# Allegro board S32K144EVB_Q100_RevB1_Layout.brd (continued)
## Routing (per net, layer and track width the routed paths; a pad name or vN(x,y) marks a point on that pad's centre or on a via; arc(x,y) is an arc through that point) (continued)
P3V3: length 34.3
  TOP w0.381: U15.5 39.68,35.09 ; U15.5 39.68,34.14 ; U15.5 38.99,35.15 ; U15.5 38.99,34.08 ; U15.5 39.68,34.61 ; 42.67,31.97 TP13.1 ; TP13.1 42.56,32.44 ; TP13.1 43.6,32.91 ; TP13.1 43.13,31.87 ; TP13.1 42.67,32.91 ; TP13.1 43.6,31.97 ; TP13.1 43.13,33.01 ; TP13.1 43.71,32.44 ; J10.1 40.65,29.57 ; J10.1 39.57,30.65 ; J10.1 40.65,30.65 ; J10.1 40.65,28.49 ; J10.1 39.57,28.49 ; C24.1 44.04,30.33 ; C24.1 44.04,30.97 ; C24.1 42.51,30.33 ; C24.1 42.51,30.97 ; C24.1 43.27,30.97 ; R63.1 40.1,26.93 ; R63.1 39.46,27.69 ; R63.1 40.1,27.69
  L3_MIX w0.508: J3.7 36.54,5.12 ; J3.7 36.3,5.9 ; J3.7 34.51,5.12 ; J3.7 35.52,6.13 ; J3.7 34.74,5.9 ; J3.7 36.3,4.34 ; J3.7 34.74,4.34 ; 39.57,28.49 J10.1 ; J10.1 40.65,29.57 ; J10.1 40.39,28.74 ; J10.1 38.74,28.74 ; J10.1 40.39,30.39
P3V3_SDA: length 36
  TOP w0.178: U9.5 33.64,39.65 v1(33.64,39.64)
  TOP w0.254: R15.1 30.3,45.46 v1(30.04,45.2) ; 30.5,36.03 C19.1 31.01,35.52 ; U4.1 28.54,45.51 v1(28.2,45.85) 28.45,46.1 U2.7 ; C18.1 29.42,36.54 ; C18.1 29.93,36.03 ; C18.1 29.42,35.52 ; U8.1 v1(19.51,43.09) ; R1.2 v1(6.4,52.28) ; 9.19,50.89 R3.1 ; U7.1 28.13,41.66 27.86,41.93 v1(27.83,41.93) ; 15.64,40.52 16.01,40.88 16.58,40.88 16.94,40.52 ; J12.1 17.92,28.09 C26.1 ; 30.51,37.11 R52.1 ; U10.1 v1(27.41,38.62) ; v1(15.03,27.14) 14.52,27.14 14.44,27.06 R77.1 ; 9.19,49.94 C3.1 ; U1.1 9.07,51.26 ; U8.11 v1(16.65,37.9)
  TOP w0.508: J9.1 13.35,40.52 C12.1 15.64,40.52 ; R12.1 v1(25.56,46.72) ; R30.1 v1(30.99,42.98) ; v1(37.61,42.64) C10.1 37.61,41.46 R39.2 R42.1 ; R60.1 v1(11.75,37.33)
  TOP w0.635: C6.1 17.76,44.83 C7.1 18.65,43.95 v1(19.51,43.09)
  BOTTOM w0.254: 10.78,38.9 J9.1 ; J9.1 12.69,38.9 ; J9.1 11.73,37.94 ; 17.32,27.37 J12.1 18.65,28.09
  vias: v1(8.76,50.56) v1(29.29,36.97)
P5V0: length 35.8
  TOP w0.381: C21.1 31.6,32.09 ; C21.1 31.6,31.45 ; C21.1 30.84,31.45 ; TP14.1 31.72,29.54 ; TP14.1 30.78,29.54 ; TP14.1 31.82,29.07 ; TP14.1 30.78,28.6 ; TP14.1 30.68,29.07 ; TP14.1 31.72,28.6 ; TP14.1 31.25,28.5 ; TP14.1 31.25,29.64 ; 34.49,28.49 J10.3 ; J10.3 33.66,28.74 ; J10.3 33.66,30.39 ; J10.3 34.49,30.65 ; J10.3 33.41,29.57 ; 31.74,31.44 C22.1 ; C22.1 33.27,31.44 ; C22.1 32.5,31.44 ; C22.1 31.74,32.08 ; 33.9,26.93 R64.1 ; R64.1 33.9,27.69 ; R64.1 34.54,27.69
  TOP w0.635: R169.1 v3(34.1,34.61) ; U15.1 v3(35.25,34.61)
  L3_MIX w0.381: J3.9 38.84,5.9 ; J3.9 38.06,6.13 ; J3.9 37.28,5.9 ; J3.9 39.08,5.12 ; J3.9 37.28,4.34 ; J3.9 38.84,4.34
  BOTTOM w0.635: J10.3 35.57,29.57 ; J10.3 34.49,28.49 ; J10.3 33.41,29.57 ; J10.3 34.49,30.65 ; J107.2 25.24,30.65 ; J107.2 26.32,29.57 ; J107.2 24.16,29.57 ; J107.2 25.24,28.49
  vias: v1(41.68,26.63) v1(42,27.41) v1(42.39,26.64)
P5V0_SDA_USB_CONN_VBUS: length 5.6
  TOP w0.152: 7.34,41.44 7.34,41.45 D17.2 8.02,40.99
  TOP w0.356: 5.64,42.72 J7.1
  TOP w0.381: L1.1 8.02,40.99
  TOP w0.635: 5.64,42.72 6.92,41.44 7.34,41.44
P5V_SBC: length 59.2
  TOP w0.203: U28.1 44.26,24.42 43.79,23.95 43.79,23.39 v1(44.21,22.97) ; U26.1 36.78,24.42 ; U30.1 40.72,24.44 40.31,24.03 40.31,23.32 v1(40.65,22.97) ; 21.62,17.74 U19.5 ; U32.1 v1(43.74,19.05)
  TOP w0.254: U29.1 v1(48.98,24.65) 48.98,25.06 49.62,25.69 ; R560.2 41.24,22.9 ; R560.2 41.24,21.88 ; R560.2 v1(40.65,22.97) ; R560.2 40.73,22.39 ; R558.2 v1(44.21,22.97) ; R536.1 36.28,22.9 ; R536.1 34.76,22.9 ; R536.1 35.52,23.53 ; R562.2 v1(47.97,18.67) ; R556.2 37.68,22.9 ; R556.2 37.17,22.39 ; R556.2 v1(37.1,22.97) ; R556.2 37.68,21.88 ; 34.28,22.91 R538.1 33.65,23.67 ; 33.65,23.79 R530.1 33.65,25.32 ; 49.62,22.58 49.62,22.56 49.53,22.47 49.57,22.43 49.57,22.15 49.38,21.96 49.02,21.96 v1(48.94,21.88) 48.94,21.65 49.16,21.43 U31.1 ; R564.1 49.19,19.34 48.92,19.07 v1(48.92,18.77) 49.04,18.65 49.24,18.65 49.57,18.32 U33.1
  TOP w0.356: 21.62,17.74 21.82,17.74 22.5,17.05
  TOP w0.381: R530.1 v1(34.58,24.56)
  TOP w0.508: R538.1 v1(33.65,21.83)
  TOP w0.762: v2(24.02,14.14) TP15.1 24.03,15.62 R535.1 22.5,17.05
  TOP w0.889: J107.1 28.95,30.74 C27.1
  L3_MIX w1.27: J107.1 24.02,25.8 v2(24.02,14.14)
  BOTTOM w0.508: J107.1 28.86,30.65 ; J107.1 28.86,28.49 ; J107.1 27.78,30.65 ; J107.1 27.78,28.49 ; J107.1 28.86,29.57
P5V_SDA: length 24.5
  TOP w0.254: 22.16,45.36 R14.1 22.67,45.86 ; U8.6 16.74,41.43 v1(16.62,41.43)
  TOP w0.508: C25.1 v1(8.15,29.82) ; C15.1 7.5,37.47 7.18,37.79 v1(7.18,38.88) L1.2 ; U11.1 v1(8.08,31.93) ; R70.1 v1(8.14,31.06) ; R57.1 v1(26.57,37.38) ; C11.1 v1(9.35,38.48)
  L3_MIX w0.635: v1(16.62,41.43) v1(16.62,45.82)
  BOTTOM w0.254: v1(26.57,37.38) 25.9,38.05 25.9,38.08 25.53,38.45 25.5,38.45 24.74,39.21 23.1,39.21 22.47,39.84 22.47,45.44 v1(22.02,45.89)
  vias: v1(7.36,46.09) v1(8.23,46.11) v1(9.16,46.11)
P5V_SDA_PSW: length 26.2
  TOP w0.508: v1(7.96,27.05) 7.26,27.75 7.26,34.41 8.08,35.23 U11.6
  BOTTOM w0.508: v1(7.96,27.05) 9.59,27.05 11.2,25.44 18.58,25.44 J107.3
VBATT: length 68.8
  TOP w0.381: D9.A 26.48,12.42 ; D9.A 24.88,12.42 ; D9.A 25.68,12.42 ; D9.A 24.88,11.62 ; D9.A 26.48,10.82 ; D9.A 26.48,11.62 ; D9.A 24.88,10.82 ; D9.A 25.68,10.82 ; TP38.1 26.15,8.58 ; TP38.1 26.26,9.05 ; TP38.1 26.15,9.52 ; TP38.1 25.69,9.62 ; TP38.1 25.69,8.48 ; TP38.1 25.22,9.52 ; TP38.1 25.22,8.58 ; TP38.1 25.12,9.05 ; J16.1 23.2,7.96 ; J16.1 23.2,9.88 ; J16.1 21.83,7.96 ; J16.1 22.29,11.8 ; J16.1 22.75,11.8 ; J16.1 22.29,7.96 ; J16.1 23.2,10.84 ; J16.1 23.2,11.8
  BOTTOM w1.016: v2(23.93,7.2) 12.91,7.2 11.23,8.89 10.21,8.89 4.8,14.29 4.8,31.29 J11.2
VDD: length 128.2
  TOP w0.203: U30.8 41.36,25.28 40.91,25.73 v1(40.91,25.71) ; v1(44.44,20.36) 44.53,20.26 44.66,20.26 44.91,20.01 U32.8 ; U26.8 37.38,25.07 v1(37.12,25.33) ; U28.8 44.9,25.42 v1(44.51,25.81)
  TOP w0.254: R63.2 37.94,27.69 ; R63.2 37.3,26.93 ; R63.2 37.3,27.69 ; J10.2 37.85,28.74 ; J10.2 37.03,28.49 ; J10.2 35.95,29.57 ; J10.2 37.85,30.39 ; J10.2 36.2,30.39 ; J10.2 37.03,30.65 ; J10.2 38.11,29.57 ; J10.2 36.2,28.74 ; R64.2 36.06,27.69 ; R64.2 36.7,26.93 ; R64.2 36.7,27.69 ; U29.6 v1(51.19,24.65) ; U33.6 v1(51.27,18.32) ; v1(52.71,21.44) C537.1 51.39,21.44 51.38,21.43 U31.6
  TOP w0.508: J15.1 47.34,30.64 ; J15.1 47.34,28.51 ; J15.1 46.27,30.64 ; J15.1 48.4,28.51 ; J15.1 48.4,29.58 ; J15.1 46.27,29.58 ; J15.1 46.27,28.51 ; J15.1 48.4,30.64 ; 47.72,32.58 R117.1 ; R117.1 48.35,31.82 ; R117.1 48.35,33.34 ; 47.4,37.77 R121.1 ; R121.1 48.17,37.13 ; R121.1 48.93,37.77 ; 42.4,36.09 TP9.1 ; TP9.1 43.87,37.57 ; TP9.1 43.13,37.78 ; TP9.1 44.09,36.83 ; TP9.1 43.87,36.09 ; TP9.1 42.4,37.57 ; TP9.1 42.18,36.83 ; SW3.4 v1(124.13,19.63) ; SW2.4 v1(124.13,30.97) ; SW2.2 v1(124.13,38.79) ; 46.47,26.94 R56.2 ; R56.2 47.1,26.18 ; R56.2 47.1,27.7 ; SW3.2 v1(124.13,27.21) ; J14.1 54.49,38.57 ; J14.1 54.49,39.29 ; J14.1 53.16,38.57 ; SH1.2 40.46,38.74 ; SH1.2 40.46,37.55 ; SH1.2 41.15,38.15
  TOP w0.635: J3.3 C49.1 ; D11.A3 v3(119.42,15.91) ; D11.A2 v3(121.52,15.9) ; D11.A1 v3(123.62,16.02)
  L3_MIX w0.508: 42.18,36.83 TP9.1 ; TP9.1 43.87,37.57 ; TP9.1 42.4,36.09 ; TP9.1 43.13,37.78 ; TP9.1 44.09,36.83 ; TP9.1 42.4,37.57 ; TP9.1 43.13,35.88 ; TP9.1 43.87,36.09 ; J10.2 37.85,30.39 ; J10.2 36.2,28.74 ; J10.2 36.2,30.39 ; J10.2 37.03,30.65 ; J10.2 35.95,29.57 ; 29.66,5.9 J3.3 ; J3.3 29.43,5.12 ; J3.3 29.66,4.34 ; J3.3 30.44,6.13 ; J3.3 30.44,4.1
  BOTTOM w0.381: 83,1.8 J5.10 ; J5.10 84.56,3.36 ; J5.10 83.78,1.56 ; J5.10 84.8,2.58 ; J5.10 84.56,1.8 ; J5.10 83,3.36 ; J5.10 82.77,2.58 ; J5.10 83.78,3.59 ; 122.78,28.47 TP16.1 ; TP16.1 123.52,28.25 ; TP16.1 122.78,29.94 ; TP16.1 124.47,29.2 ; TP16.1 124.25,28.47 ; TP16.1 123.52,30.16 ; TP16.1 122.56,29.2 ; TP16.1 124.25,29.94 ; 80.46,55.14 J6.10 ; J6.10 81.24,54.9 ; J6.10 82.26,55.92 ; J6.10 80.23,55.92 ; J6.10 82.02,55.14 ; J6.10 80.46,56.7 ; J6.10 82.02,56.7 ; J6.10 81.24,56.93 ; TP4.1 114.91,55.87 ; TP4.1 113,55.87 ; TP4.1 113.96,56.82 ; TP4.1 113.22,56.6 ; TP4.1 113.96,54.91 ; TP4.1 114.69,55.13 ; TP4.1 114.69,56.6 ; TP4.1 113.22,55.13 ; R13.1 121.85,47.77 ; R13.1 120.84,49.8 ; R13.1 120.84,47.77 ; R13.1 119.82,49.8 ; R13.1 119.82,47.77 ; R13.1 119.82,48.78 ; R13.1 121.85,49.8 ; R13.1 121.85,48.78
  BOTTOM w0.635: J15.1 48.4,29.58 ; J15.1 46.27,29.58 ; J15.1 47.34,28.51
  vias: v1(70.2,1.09) v1(70.21,3.11) v1(70.23,2.07) v1(71.4,1.12) v1(71.43,3.09) v1(71.42,2.06)
VDD_MCU: length 75.7
  TOP w0.254: R103.1 58.95,32.98 ; R103.1 58.18,33.62 ; R103.1 57.42,33.62 ; R103.1 58.95,33.62 ; R103.1 57.42,32.98 ; C131.1 58.87,37.66 ; C131.1 59.51,36.89 ; C131.1 59.51,36.13 ; C131.1 58.87,36.13 ; C131.1 59.51,37.66 ; 59.04,33.63 R99.1 ; R99.1 60.56,32.99 ; R99.1 60.56,33.63 ; R99.1 59.8,33.63 ; R99.1 59.04,32.99 ; 62.15,32.78 C140.1 ; C140.1 62.58,32.69 ; C140.1 63,32.78 ; C140.1 63.08,33.2 ; C140.1 62.07,33.2 ; C147.1 59.51,41.83 ; C147.1 58.23,40.3 ; C147.1 58.23,41.06 ; C147.1 58.87,40.3 ; C147.1 59.51,40.3 ; C147.1 59.51,41.06 ; C147.1 58.23,41.83 ; C147.1 58.87,41.83 ; C43.1 59.51,38.57 ; C43.1 59.51,39.33 ; C43.1 58.87,39.33 ; C43.1 58.87,37.81 ; C43.1 59.51,37.81 ; 75.37,19.77 U17.38 ; 84.68,28.16 U17.61 81.54,28.16 ; 63.16,33.2 C145.1 ; C145.1 64.09,32.78 ; C145.1 63.24,32.78 ; C145.1 63.67,32.69 ; C145.1 64.18,33.2 ; C129.1 59.51,35.98 ; C129.1 58.87,34.46 ; C129.1 58.87,35.98 ; C129.1 59.51,35.22 ; C129.1 59.51,34.46 ; 60.97,33.2 C144.1 ; C144.1 61.06,33.63 ; C144.1 61.06,32.78 ; C144.1 61.48,32.69 ; C144.1 61.91,32.78 ; C144.1 61.99,33.2 ; 75.87,38.75 U17.87
  TOP w0.381: C142.1 75.62,39 75.87,38.75 ; 75.37,19.77 75.62,19.51 C141.1 ; 84.68,28.16 84.91,28.39 C143.1
  TOP w0.508: C146.1 86.48,28.55 86.31,28.39 C143.1
  TOP w0.635: C141.1 75.62,18.53 v3(75.2,18.11) 75.24,18.07 C137.1 ; v3(75.12,28.16) 81.54,28.16 ; C133.1 77.02,41.8 v3(75.62,40.4) C142.1
  TOP w0.762: R117.2 J15.2
  BOTTOM w0.508: v1(68.89,30.41) v3(65.79,30.41)
  BOTTOM w1.016: J15.2 49.88,31.27 51.29,32.68 51.44,32.68 52,33.25 55.53,33.25 55.98,33.69 56.24,33.95 v2(57.38,33.95)
  vias: v3(75.12,30.66)
VIN: length 28.4
  TOP w0.762: J3.1 27.9,7.51 29.8,9.41 34.04,9.41 35.78,7.67 43.13,7.67 J3.15
  TOP w0.889: J3.15 D13.A
ADC0_SE12: length 72.4
  TOP w0.16: R13.2 C5.1 116.26,44.77 116.26,44.76 TP5.1 116.26,30.84 114.98,29.56 100.58,29.56 97.86,26.84 v1(94.68,26.84) ; R164.2 v1(80.45,13.79)
  L3_MIX w0.16: v1(94.68,26.84) 94.68,25.27 94.03,24.62 v1(94.03,13.65)
  BOTTOM w0.16: v1(94.03,13.65) 93.03,13.65 92.92,13.75 89.82,13.75 89.02,14.55 85.91,14.55 84.85,13.49 82.47,13.49 82.45,13.47 80.78,13.47 v1(80.45,13.79)
AREF: length 43.9
  TOP w0.508: R109.2 55.67,44.7 53.43,46.94 40.09,46.94 39.62,46.47 35.48,46.47 32.64,49.31 27.9,49.31 J2.15
BTN0: length 58.6
  TOP w0.16: R152.2 v1(84.64,14.09) ; SW2.1 SW2.3 R44.1 119.9,31.82 119.89,31.82 C16.1 118.39,31.29 115.42,28.32 100.37,28.32 97.97,25.92 v1(93.98,25.92)
  L3_MIX w0.16: v1(93.98,25.92) 93.41,25.35 v1(93.41,14.62)
  BOTTOM w0.16: v1(93.41,14.62) 89.55,14.62 89.27,14.9 85.45,14.9 v1(84.64,14.09)
BTN1: length 61.2
  TOP w0.16: R153.2 v1(82.96,12.3) ; SW3.3 SW3.1 R74.1 C28.1 100.15,27.15 98.06,25.06 v1(95.43,25.06)
  L3_MIX w0.16: v1(94.57,12.95) 94.57,24.21 v1(95.43,25.06)
  BOTTOM w0.16: v1(82.96,12.3) 85.12,12.3 85.6,12.79 86.92,12.79 86.95,12.76 87.37,12.76 87.45,12.84 92.53,12.84 92.54,12.83 92.92,12.83 93.04,12.95 v1(94.57,12.95)
CAN_HI: length 21.5
  TOP w0.305: J13.1 1.5,21.91 1.5,20.02 2.14,19.37 3.9,19.37 4.22,19.04 TP19.1 6.75,19.04 6.87,19.16 7.95,19.16 10.37,16.74 12.09,16.74 J109.1 15.01,16.74 U19.18
CAN_LO: length 16.2
  TOP w0.305: J13.2 TP22.1 6.85,19.92 7.87,19.92 10.35,17.44 12.28,17.44 J108.1 15.02,17.24 U19.17
JTAG_TCLK/SWD_CLK: length 37
  TOP w0.16: J14.4 47.49,40.56 TP31.1 43.87,44.19 J8.2 ; R127.2 v1(69.45,44.33)
  BOTTOM w0.16: J14.4 50.52,40.56 50.49,40.53 50.49,38.55 51.28,37.75 53.36,37.75 53.68,38.07 54.51,38.09 54.52,38.09 59.28,42.85 67.96,42.85 v1(69.45,44.33)
JTAG_TDI: length 24.3
  TOP w0.16: v1(71.12,44.36) R128.2 ; R120.2 v1(49.41,45.66)
  BOTTOM w0.16: v1(71.12,44.36) 70.31,45.17 56.88,45.17 56.39,45.66 v1(49.41,45.66)
JTAG_TDO: length 29.8
  TOP w0.16: v1(73.37,45.16) 73.37,43.98 73.37,43.98 R123.2 ; R119.2 v1(47.85,46.31)
  BOTTOM w0.16: v1(47.85,46.31) 48.22,46.67 57.01,46.67 57.35,46.33 71.58,46.33 72.75,45.16 v1(73.37,45.16)
JTAG_TMS/SWD_DIO_PTA4: length 27.3
  TOP w0.16: v1(66.34,43.33) R122.2 ; J14.2 R121.2 TP34.1 46.34,39.29 J106.2
  BOTTOM w0.16: J14.2 52.79,38.39 53.52,38.39 53.54,38.41 54.01,38.42 58.92,43.33 v1(66.34,43.33)
LEDRGB_BLUE: length 4.9
  TOP w0.16: D11.C3 TP28.1 v1(117.69,7.48) R95.1
LEDRGB_GREEN: length 7.7
  TOP w0.16: R96.1 v1(117.67,5.7) 119.74,5.7 TP29.1 D11.C2
LEDRGB_RED: length 10.5
  TOP w0.16: D11.C1 TP30.1 v1(122.71,6.58) 120.06,3.93 R97.1
LIN: length 29.8
  TOP w0.406: U21.6 R171.1 R80.1 TP18.1 5.51,26.03 C17.1 J11.1
LIN_RX: length 43.3
  TOP w0.16: R130.1 69.87,14.15 68.15,12.43 51.99,12.43 51.65,12.09 46.93,12.09 45.95,13.07 45.95,15.23 47.99,17.27 v1(48.5,17.27) ; v1(48.5,22.75) 48.12,23.13 48.12,24.05 46.84,25.33 46.28,25.33 45.98,25.63 45.48,25.63 45.3,25.46 U28.7
  L3_MIX w0.16: v1(48.5,17.27) 48.86,17.63 49.03,17.63 49.38,17.98 49.38,19.43 48.48,20.32 48.48,22.07 48.5,22.09 v1(48.5,22.75)
LIN_RX_LS: length 35.7
  TOP w0.16: v1(32.12,21.85) R538.2 TP35.1 29.78,22.91 29.76,22.89 U21.1 ; U28.2 v1(44.37,23.77)
  L3_MIX w0.16: v1(43.88,14.35) 43.88,16.46 44.9,17.48 44.9,22.74 44.82,22.81 44.82,23.32 v1(44.37,23.77) ; v1(32.12,21.85) 32.6,21.37 32.6,19.72 32.43,19.56 v1(32.43,13.88)
  BOTTOM w0.16: v1(32.43,13.88) 43.41,13.88 v1(43.88,14.35)
LIN_SLP: length 43.5
  TOP w0.16: v1(48.02,24.81) 47.17,25.66 47.04,25.66 47.04,25.67 46.42,25.67 46.05,26.04 45.17,26.04 44.89,26.32 42.72,26.32 42.57,26.17 39.75,26.17 39.73,26.15 32.85,26.15 32.12,25.43 R530.2 29.98,24.56 29.59,24.16 U21.2 ; R529.1 61.4,18.66 59.99,17.26 55.17,17.26 54.13,18.3 v1(52.36,18.3)
  L3_MIX w0.16: v1(52.36,18.3) 51.57,19.09 51.57,22.12 52.2,22.74 52.2,24.29 51.35,25.14 48.35,25.14 v1(48.02,24.81)
LIN_TX: length 31.2
  TOP w0.16: v1(51.74,16.58) 52.07,16.25 52.07,16.05 55.35,12.76 64.75,12.76 65.32,13.33 67.34,13.33 68.2,14.18 R131.1 ; v1(47.66,23.86) 46.53,24.99 46.14,24.99 46.06,25.07 U28.6
  L3_MIX w0.16: v1(51.74,16.58) 50.14,18.18 50.14,21.76 48.39,23.51 48.01,23.51 v1(47.66,23.86)
LIN_TX_LS: length 42.1
  TOP w0.16: U21.4 28.96,26.7 28.97,26.71 TP37.1 31.34,26.71 v1(32.01,26.03) ; U28.3 v1(45.3,22.98)
  L3_MIX w0.16: v1(32.35,12.54) 32.09,12.8 32.09,13.58 31.97,13.69 31.97,14.07 32.09,14.19 32.09,19.45 31.62,19.92 31.62,25.63 v1(32.01,26.03) ; v1(44.02,12.39) 44.35,12.72 44.35,14.53 44.33,14.55 44.33,16.43 44.37,16.48 45.3,17.41 v1(45.3,22.98)
  BOTTOM w0.16: v1(32.35,12.54) 43.41,12.54 43.56,12.39 v1(44.02,12.39)
LVLRST_EN: length 1.4
  TOP w0.16: R1.1 U1.5
MIC2005_CSLEW: length 1.8
  TOP w0.16: U11.5 C15.2
POWER_EN: length 15.7
  TOP w0.16: R69.1 v1(12.64,32.91) ; v1(20.95,42.96) 20.95,42.91 U8.31
  BOTTOM w0.16: v1(20.95,42.96) 20.63,42.63 20.38,42.63 17.25,39.5 16.73,39.5 15.65,38.42 15.65,37.09 12.64,34.08 v1(12.64,32.91)
PTA0: length 53.4
  TOP w0.16: U17.79 79.87,38.25 80.37,38.76 85.13,38.76 87.73,41.35 v1(87.73,41.81)
  L3_MIX w0.16: J5.7 83.73,7.6 86.41,7.6 89.24,10.43 89.24,14.62 88.55,15.31 88.55,27.17 87.84,27.88 87.84,31.96 87.55,32.26 87.55,41.07 87.4,41.22 87.4,41.48 v1(87.73,41.81)
PTA1: length 59
  TOP w0.16: U17.78 80.37,37.97 80.81,38.4 85.7,38.4 89.28,41.99 v1(89.74,41.99)
  L3_MIX w0.16: v1(89.74,41.99) 89.74,40.81 89.86,40.69 89.86,37.42 88.95,36.52 88.95,36.14 89.32,35.77 89.32,28.97 89.89,28.4 89.89,24.75 89.8,24.66 89.8,22.38 90.31,21.87 90.42,21.76 90.42,10.25 v1(89.89,9.72)
  BOTTOM w0.16: J5.5 79.44,5.86 79.44,6.28 80.35,7.19 87.36,7.19 v1(89.89,9.72)
PTA2: length 17.6
  TOP w0.16: SH11.1 91.73,35.67 v1(91.48,35.41) 91,35.9 91,36.64 91.61,37.26 R542.1 91.61,38.31 91.61,38.32 R540.2 ; v1(81.85,34.16) U17.73
  BOTTOM w0.16: v1(81.85,34.16) 84.64,34.16 86.05,35.56 90.82,35.56 90.97,35.41 v1(91.48,35.41)
PTA3: length 18.2
  TOP w0.16: v1(85.36,33.57) 84.9,33.57 84.81,33.66 U17.72 ; v1(91.53,34.19) SH12.1 93.52,34.9 95.03,34.9 96.37,36.24 R541.1 96.37,38.19 R539.2
  BOTTOM w0.16: v1(85.36,33.57) 86.09,34.3 89.95,34.3 90.19,34.55 91.17,34.55 v1(91.53,34.19)
PTA4: length 8.5
  TOP w0.16: U17.98 70.37,38.21 67.77,40.82 R122.1 v1(66.43,41.8) R546.2
PTA6: length 6.9
  TOP w0.16: R147.2 87.16,25.54 v1(86.47,26.23) 85.09,26.23 84.66,26.66 U17.58
PTA7: length 33.9
  TOP w0.16: v1(84.85,25.65) 84.35,26.16 U17.57
  L3_MIX w0.16: J5.9 85.55,6.89 87.03,6.89 88.97,8.83 90.33,8.83 91.61,10.11 91.61,22.67 91.23,23.05 v1(91.23,25.65)
  BOTTOM w0.16: v1(84.85,25.65) v1(91.23,25.65)
PTA8: length 17.5
  TOP w0.16: U17.100 v1(69.37,38.38)
  L3_MIX w0.16: v1(69.37,38.38) 68.98,38.76 68.98,47.86 71.08,49.95 J6.17
PTA9: length 20
  TOP w0.16: U17.99 v1(69.87,35.64)
  L3_MIX w0.16: v1(69.87,35.64) 68.03,37.47 68.03,44.46 68.01,44.48 68.01,44.86 68.03,44.89 68.03,51.5 68.54,52.01 J6.19
PTA10: length 7
  TOP w0.16: U17.92 73.37,40.27 v1(72.86,40.78) 73.37,41.29 R123.1 R545.2
PTA11: length 31
  TOP w0.16: U17.91 v1(73.87,38.2)
  L3_MIX w0.16: v1(61.41,40.4) 61.41,51.22 62.17,51.98 62.17,54.63 J1.2
  BOTTOM w0.16: v1(61.41,40.4) 62,39.8 62.77,39.8 63.74,38.83 64.12,38.83 64.13,38.84 69.85,38.84 70.48,38.2 v1(73.87,38.2)
PTA12: length 21.2
  TOP w0.16: U17.90 v1(74.37,38.9)
  L3_MIX w0.16: J6.16 72.53,54.82 72.53,52.32 75.48,49.36 75.48,43.9 74.37,42.79 v1(74.37,38.9)
PTA13: length 20.2
  TOP w0.16: U17.89 v1(74.87,38.2)
  L3_MIX w0.16: v1(74.87,38.2) 74.87,42.68 75.82,43.63 75.82,51.66 75.07,52.42 75.07,54.82 J6.14
PTA14: length 66
  TOP w0.16: v1(74.38,46.62) 75.8,45.2 75.8,41.43 75.04,40.67 75.04,38.88 75.37,38.55 U17.88
  BOTTOM w0.16: J2.16 25.14,54.62 25.14,53.06 26.89,51.32 37.63,51.32 41.52,47.43 73.57,47.43 v1(74.38,46.62)
PTA15: length 8.1
  TOP w0.16: R167.1 81.31,41.16 81.57,40.9 81.57,40.38 81.3,40.11 78.7,40.11 78.14,39.54 78.14,38.38 77.87,38.12 U17.83
PTA16: length 8.3
  TOP w0.16: U17.82 78.37,37.94 78.54,38.11 78.54,39.22 79.09,39.77 81.44,39.77 81.9,40.24 81.9,40.89 82.36,41.35 82.4,41.35 82.86,41.81 R165.1
PTA17: length 53.4
  TOP w0.16: v1(81.03,29.69) 82.07,28.66 U17.62
  L3_MIX w0.16: v1(58.73,30.47) 58.73,51.82 59.63,52.73 59.63,54.63 J1.4
  BOTTOM w0.16: v1(58.73,30.47) 58.73,29.7 59.19,29.24 65.51,29.24 66.84,27.91 70.06,27.91 71.84,29.69 v1(81.03,29.69)
PTB0: length 48.5
  TOP w0.16: v1(85.96,12.32) 85.42,11.79 67.36,11.79 67.36,11.78 67.02,11.78 64.25,9.02 58.14,9.02 55.84,6.72 J4.5 ; U17.54 84.69,24.66 85.55,23.79 85.55,20.26 85.96,19.85 v1(85.96,18.82)
  L3_MIX w0.16: v1(85.96,18.82) v1(85.96,12.32)
PTB1: length 44.8
  TOP w0.16: v1(84.19,9.67) 83.38,10.48 67.81,10.48 64.87,7.54 60.81,7.54 J4.7 ; U17.53 84.37,24.16 85.15,23.38 v1(85.15,19.61)
  L3_MIX w0.16: v1(84.19,9.67) 85.15,10.63 v1(85.15,19.61)
PTB2: length 84
  TOP w0.16: U17.48 v1(80.37,19.63) ; J2.11 31.06,51.24 31.73,51.24 31.74,51.23 32.4,51.23 32.4,51.24 32.72,51.24 33.28,51.24 33.95,50.58 34.14,50.38 39.52,50.38 40.38,49.52 72.04,49.52 72.24,49.33 72.24,49.33 72.66,48.91 79.12,48.91 v1(79.51,48.51)
  L3_MIX w0.16: v1(79.51,48.51) 79.51,42.49 79.98,42.02 79.98,39.51 80.22,39.27 80.22,34.67 79.82,34.27 79.82,24.24 80.37,23.68 v1(80.37,19.63)
PTB3: length 79.6
  TOP w0.16: v1(79.03,51.36) 70.08,51.36 69.02,50.3 40.55,50.3 39.8,51.05 34.42,51.05 33.56,51.91 32.92,51.91 J2.9 ; v1(79.89,22.84) 79.89,21.42 U17.47
  L3_MIX w0.16: v1(79.89,22.84) 79.25,23.48 79.25,42.03 79.03,42.24 v1(79.03,51.36)
PTB4: length 67.6
  TOP w0.16: v1(69.06,24.9) 69.53,24.9 70.37,24.05 U17.28 ; J2.7 35.65,51.73 40.08,51.73 40.83,50.98 66.86,50.98 v1(67.83,51.94)
  L3_MIX w0.16: v1(69.06,24.9) 69.39,25.22 69.39,34.52 67.57,36.34 67.57,41.33 67.57,41.33 67.57,43.7 67.5,43.77 67.5,51.62 v1(67.83,51.94)
PTB5: length 84.7
  TOP w0.16: U17.27 69.87,20.18 69.45,19.76 67.76,19.76 63.94,15.95 v1(63.48,15.95)
  L3_MIX w0.16: J2.5 36.54,51.93 40.18,48.29 42.23,48.29 45.05,45.48 45.05,36.44 46.05,35.44 46.05,34.38 43.9,32.23 43.9,28.99 44.28,28.61 44.28,27.72 43.72,27.16 43.72,19.82 44.2,19.34 44.2,17.26 43.42,16.48 43.42,8.97 v1(44.72,7.66)
  BOTTOM w0.16: v1(63.48,15.95) 62.77,15.24 57.9,15.24 54.61,11.95 50.03,11.95 45.74,7.66 v1(44.72,7.66)
PTB6: length 6.6
  TOP w0.16: R81.2 62.92,26.3 R84.1 v1(64.48,27.08) 65.54,27.08 66.12,27.66 U17.16
PTB6_XTAL: length 6.9
  TOP w0.16: R84.2 60.38,27.08 60.33,27.13 R91.2 59.42,27.13 58.96,26.66 58.58,26.66 C127.1 57.24,26.92 Y3.2
PTB7: length 6.6
  TOP w0.16: R90.2 62.92,29.51 R88.1 v1(64.45,28.73) 65.57,28.73 66.14,28.16 U17.15
PTB7_EXTAL: length 6.9
  TOP w0.16: R88.2 60.4,28.73 60.33,28.65 R91.1 59.42,28.65 58.96,29.11 58.6,29.11 C126.1 57.27,28.92 Y3.1
PTB8: length 45.8
  TOP w0.16: U17.77 80.87,37.83 81.07,38.04 82.21,38.04 82.54,37.7 v1(85.21,37.7)
  L3_MIX w0.16: v1(85.21,37.7) v1(85.21,49.6)
  BOTTOM w0.16: J1.5 59.64,52.12 60.37,52.12 61.18,51.31 78.23,51.31 79.94,49.6 v1(85.21,49.6)
PTB9: length 45.6
  TOP w0.16: v1(84.41,36.91) U17.76
  L3_MIX w0.16: v1(84.41,48.88) 84.41,46.22 84.17,45.99 84.17,39.62 84.41,39.38 v1(84.41,36.91)
  BOTTOM w0.16: J1.7 58.58,50.64 78.15,50.64 79.91,48.88 v1(84.41,48.88)
PTB10: length 49.2
  TOP w0.16: U17.75 v1(83.12,36.43)
  L3_MIX w0.16: v1(54.72,35.59) 55.61,36.49 55.61,47.32 53.3,49.63 J1.9
  BOTTOM w0.16: v1(83.12,36.43) 83.07,36.39 64.31,36.39 64.3,36.4 59.6,36.4 58.92,35.73 55.5,35.73 55.37,35.59 v1(54.72,35.59)
PTB11: length 56.4
  TOP w0.16: U17.74 v1(84.49,34.66)
  L3_MIX w0.16: v1(54.94,32.27) 54.94,34.54 53.91,35.57 53.91,37.25 54.8,38.14 54.8,46 50.76,50.04 J1.11
  BOTTOM w0.16: v1(84.49,34.66) 82.68,34.66 82.41,34.92 80.69,34.92 79.94,35.68 71.08,35.68 70.24,34.84 69.36,34.84 69.25,34.95 66.53,34.95 63.85,32.27 v1(54.94,32.27)
PTB12: length 74.7
  TOP w0.16: v1(86.87,36.96) 86.16,36.25 86.16,33.24 85.59,32.66 85.59,32.36 84.88,31.66 U17.68
  L3_MIX w0.16: v1(53.23,35.71) 53.9,35.04 53.9,29.91 54.08,29.73 54.08,23.14 53.3,22.36 53.3,21.12 52.94,20.76 52.94,19.52 53.16,19.3 53.16,17.42 53.08,17.33 53.08,6.54 53.3,6.32 J4.3
  BOTTOM w0.16: v1(53.23,35.71) 53.71,35.71 54.38,36.39 55.21,36.39 55.22,36.4 58.59,36.4 59.26,37.08 64.58,37.08 64.59,37.06 76.28,37.06 77.38,38.16 85.66,38.16 v1(86.87,36.96)
PTB13: length 39.8
  TOP w0.16: U17.67 v1(84.41,31.16)
  L3_MIX w0.16: v1(93.05,31.54) 92.72,31.21 92.72,26.85 92.3,26.44 92.3,22.98 92.23,22.91 92.23,10.25 90.07,8.09 89.29,8.09 J5.11
  BOTTOM w0.16: v1(84.41,31.16) 86.65,31.16 86.68,31.13 90.67,31.13 91.08,31.54 v1(93.05,31.54)
PTB14: length 66
  TOP w0.16: U17.66 84.71,30.66 85.97,31.92 85.97,32.56 86.5,33.09 86.5,34.72 v1(86.87,35.1) 87.05,35.28 R124.1
  L3_MIX w0.16: v1(86.53,11.67) 86.53,12.77 86.36,12.94 86.36,13.6 86.48,13.72 86.48,23.27 85.56,24.18 85.56,33.12 85.64,33.19 85.65,33.19 85.92,33.46 85.92,33.85 85.77,34 v1(86.87,35.1)
  BOTTOM w0.16: v1(86.53,11.67) 65.03,11.67 59.66,6.3 59.66,3.85 J4.8
PTB15: length 61.9
  TOP w0.16: U17.65 85.15,30.16 86.46,31.46 86.46,32.57 86.96,33.07 v1(86.96,33.6) 87.25,33.6 R125.1
  L3_MIX w0.16: v1(86.96,33.6) 85.94,32.58 85.94,25.19 86.82,24.32 86.82,13.58 86.7,13.46 86.7,13.08 86.99,12.79 86.99,11.02 v1(85.91,9.93)
  BOTTOM w0.16: v1(85.91,9.93) 85.58,10.26 76.18,10.26 75.71,9.78 65.84,9.78 62.2,6.14 62.2,3.85 J4.10
PTB16: length 57.8
  TOP w0.16: R126.1 v1(87.01,31.93) 87.01,31.21 85.45,29.66 U17.64
  L3_MIX w0.16: v1(86.99,9.77) 87.62,10.4 87.62,24.71 86.97,25.36 86.97,28.99 86.42,29.54 86.42,31.34 v1(87.01,31.93)
  BOTTOM w0.16: v1(86.99,9.77) 86.44,9.21 82.92,9.21 82.37,9.76 76.6,9.76 75.23,8.39 70.79,8.39 70.6,8.58 70.24,8.58 70.02,8.35 66.82,8.35 64.75,6.28 64.75,3.87 J4.12
PTB17: length 61.8
  TOP w0.16: J4.6 57.12,3.85 57.12,6.5 58.67,8.05 64.11,8.05 67.5,11.45 86.1,11.45 86.34,11.21 86.72,11.21 86.96,11.45 87.53,11.45 v1(88.15,12.08) ; U17.63 85.89,29.16 v1(86.88,30.15) 86.98,30.25 R129.2
  L3_MIX w0.16: v1(86.88,30.15) 87.41,29.62 87.41,26.35 88.15,25.6 v1(88.15,12.08)
PTC0: length 25.9
  TOP w0.16: R534.1 v1(95.77,14.49) ; U17.40 76.37,20.37 77.18,19.56 v1(77.18,17.45) R146.2
  BOTTOM w0.16: v1(95.77,14.49) 93.65,16.61 78.03,16.61 v1(77.18,17.45)
PTC1: length 62.4
  TOP w0.16: J5.13 88.86,6.16 88.09,6.94 78.58,6.94 77.9,6.26 v1(76.87,6.26) ; v1(95.65,32.01) R525.2 96.67,32.86 96.67,32.86 R172.2 ; U17.39 75.87,20.31 76.22,19.96 v1(76.22,16.26)
  L3_MIX w0.16: J5.13 91.03,7.28 91.33,7.28 93.49,9.45 93.49,11.16 95.22,12.88 95.22,21.73 96.15,22.67 96.15,31.51 v1(95.65,32.01) ; v1(76.22,16.26) 76.22,14.27 75.94,13.99 75.94,7.18 v1(76.87,6.26)
PTC2: length 46.7
  TOP w0.16: R528.2 R527.2 v1(94.65,11.19) ; J5.15 91.4,6.16 89.66,7.9 77.86,7.9 77.28,7.33 73.05,7.33 v1(71.06,9.32) ; v1(71.37,20.09) U17.30
  L3_MIX w0.16: v1(94.65,11.19) 94.65,8.37 J5.15 ; v1(71.37,20.09) 71.37,18 71.18,17.81 71.18,14.98 70.76,14.56 70.76,13.28 71.06,12.98 v1(71.06,9.32)
PTC3: length 74.1
  TOP w0.16: R132.2 v1(66.52,17.36) 68.31,19.15 69.85,19.15 70.87,20.17 U17.29 ; R533.1 v1(95.69,30.39) ; v1(67.28,6.89) 67.28,3.84 J4.16
  L3_MIX w0.16: v1(95.69,30.39) 95.06,29.76 95.06,28.22 92.98,26.14 92.98,22.7 92.95,22.67 92.95,13.8 93.19,13.55 93.19,13.03 93.03,12.87 v1(93.03,10.32) ; v1(67.28,6.89) 67.28,16.61 v1(66.52,17.36)
  BOTTOM w0.16: J4.16 70.05,4.08 70.05,5.37 70.93,6.25 76.06,6.25 76.87,7.07 79.16,7.07 79.82,7.72 86.59,7.72 89.19,10.32 v1(93.03,10.32)
PTC4: length 68
  TOP w0.16: R127.1 v1(69.45,40.92) 71.37,39 U17.96
  L3_MIX w0.16: v1(69.45,40.92) 70.39,39.98 70.39,16.1 v1(70.72,15.77)
  BOTTOM w0.16: J3.12 41.87,3.85 41.87,5.61 43.3,7.04 45.87,7.04 49.79,10.96 54.91,10.96 58.78,14.82 69.77,14.82 v1(70.72,15.77)
PTC5: length 65.8
  TOP w0.16: R128.1 v1(71.12,40.83) 71.12,40.11 71.87,39.36 U17.95
  L3_MIX w0.16: v1(71.12,40.83) 71.12,40.37 71.13,40.37 v1(71.13,22.99)
  BOTTOM w0.16: J3.10 39.34,3.86 39.34,5.62 42.05,8.33 45.53,8.33 51.56,14.37 51.84,14.37 53.43,15.95 53.43,16.23 54.16,16.96 60.82,16.96 61.84,17.99 65.38,17.99 70.38,22.99 v1(71.13,22.99)
PTC6: length 76.8
  TOP w0.16: U17.81 78.87,38.93 79.38,39.43 81.58,39.43 81.94,39.79 83.5,39.79 v1(84.63,40.93) 84.66,40.96 R161.1 ; v1(61.59,9.65) 57.43,9.65 54.57,6.79 54.57,3.85 J4.4
  L3_MIX w0.16: v1(61.59,9.65) 61.59,15.04 63.14,16.59 63.14,34.09 63.41,34.36 v1(63.41,41.18)
  BOTTOM w0.16: v1(84.63,40.93) 84.17,40.93 83.97,41.13 75,41.13 74.14,40.27 66.77,40.27 65.86,41.18 v1(63.41,41.18)
PTC7: length 80.6
  TOP w0.16: U17.80 79.37,38.57 79.89,39.09 81.72,39.09 82.01,39.39 84.86,39.39 v1(86.34,40.87) R162.1 ; v1(60.25,10.42) 55.49,10.42 52.04,6.96 52.04,3.85 J4.2
  L3_MIX w0.16: v1(62.75,40.6) 62.75,17 60.25,14.5 v1(60.25,10.42)
  BOTTOM w0.16: v1(62.75,40.6) 65.47,40.6 66.18,39.89 85.36,39.89 v1(86.34,40.87)
PTC8: length 31
  TOP w0.16: U17.56 v1(80.59,25.66)
  L3_MIX w0.16: J6.9 80.18,52.31 80.18,42.73 80.39,42.52 80.39,39.73 80.69,39.42 80.69,30.89 80.57,30.77 80.57,26.14 80.59,26.12 v1(80.59,25.66)
PTC9: length 33.6
  TOP w0.16: U17.55 79.97,25.16 79.16,25.97 v1(78.4,25.97)
  L3_MIX w0.16: J6.11 77.62,52.29 77.62,46.84 78.63,45.82 78.63,28.94 78.84,28.73 78.84,26.4 v1(78.4,25.97)
PTC10: length 9.5
  TOP w0.16: U17.52 84.15,23.66 84.63,23.18 v1(84.63,20.76) 84.63,19.09 87.16,16.56 R133.2
PTC11: length 11.9
  TOP w0.16: U17.51 83.12,19.76 85.58,17.3 85.58,15.68 86.51,14.76 R134.2 v1(87.16,13.27)
PTC12: length 96
  TOP w0.16: R152.1 84.59,16.56 v1(84.59,17.52) 83.98,17.52 81.37,20.13 U17.50 ; J2.10 32.8,54.58 32.8,53.03 33.57,52.25 33.7,52.25 33.93,52.25 34.79,51.39 39.94,51.39 40.69,50.64 68.57,50.64 69.83,51.9 v1(81.65,51.9)
  L3_MIX w0.16: v1(84.59,17.52) 83.7,18.42 83.7,47.48 81.65,49.53 v1(81.65,51.9)
PTC13: length 93.8
  TOP w0.16: v1(81.53,48.21) 80.49,49.24 72.8,49.24 72.58,49.47 72.58,49.47 72.18,49.86 40.52,49.86 39.66,50.72 34.28,50.72 33.42,51.58 32.58,51.58 32.26,51.58 32.26,51.57 31.88,51.57 31.87,51.58 31.71,51.58 30.18,53.11 30.18,54.66 J2.12 ; R153.1 82.96,17.16 v1(82.96,17.52) 80.87,19.61 U17.49
  L3_MIX w0.16: v1(81.53,48.21) 81.53,45.72 82.32,44.93 82.32,35.53 82.96,34.88 v1(82.96,17.52)
PTC14: length 32.3
  TOP w0.16: U17.46 79.37,18.63 v1(80.45,17.55) R164.1
  L3_MIX w0.16: v1(80.24,8.85) 80.24,12.25 79.84,12.65 79.84,16.95 v1(80.45,17.55)
  BOTTOM w0.16: J4.14 67.27,3.85 67.27,5.54 69.1,7.37 75.63,7.37 76.55,8.29 78.57,8.29 79.13,8.85 v1(80.24,8.85)
PTC15: length 35.2
  TOP w0.16: J5.20 95.27,3.79 95.27,5.34 91.81,8.8 83.32,8.8 82.37,9.76 79.2,9.76 v1(78.3,8.87) ; U17.45 v1(78.87,18.37)
  L3_MIX w0.16: v1(78.87,18.37) 78.3,17.8 v1(78.3,8.87)
PTC16: length 51.6
  TOP w0.16: J6.8 85,54.7 85,51.8 v1(89.91,46.89) ; U17.44 v1(78.37,23.95)
  L3_MIX w0.16: v1(91.83,23.95) 91.83,27.15 92.21,27.53 92.21,44.59 v1(89.91,46.89)
  BOTTOM w0.16: v1(78.37,23.95) v1(91.83,23.95)
PTC17: length 47.5
  TOP w0.16: U17.43 77.87,24.43 v1(78.38,24.94)
  L3_MIX w0.16: v1(89.43,24.94) 89.43,27.25 88.52,28.16 88.52,32.24 88.22,32.54 88.22,40.78 88.79,41.34 88.79,51.44 87.7,52.53 87.7,54.54 J6.6
  BOTTOM w0.16: v1(89.43,24.94) v1(78.38,24.94)
PTD0: length 83.9
  TOP w0.16: U17.4 66.51,33.66 66.12,34.04 66.12,38.42 65.25,39.29 v1(63.93,39.29) R156.1
  L3_MIX w0.16: v1(63.93,39.29) v1(63.93,48.06) ; v1(91.4,47.46) J6.1
  BOTTOM w0.16: v1(91.4,47.46) 90.47,47.46 90.24,47.69 89.57,47.69 89.46,47.57 79.43,47.57 78.94,48.06 v1(63.93,48.06) 55.66,48.06 53.4,50.33 40.1,50.33 37.83,52.59 37.83,54.62 J2.6
PTD1: length 48.2
  TOP w0.16: U17.3 v1(68.92,34.16)
  L3_MIX w0.16: J6.2 89.97,57.35 73.51,57.35 72.41,56.25 72.41,55.69 71.32,54.6 68.22,54.6 67.16,53.55 67.16,43.63 67.23,43.56 67.23,41.47 67.23,41.47 67.23,35.84 v1(68.92,34.16)
PTD2: length 13.8
  TOP w0.16: SH13.2 v1(91.57,32.61) ; U17.71 81.89,33.16 81.84,33.21 v1(81.38,33.21)
  BOTTOM w0.16: v1(91.57,32.61) 90.65,33.53 87.54,33.53 87.15,33.14 85.58,33.14 85.55,33.11 85.17,33.11 85.06,33.21 v1(81.38,33.21)
PTD3: length 72.8
  TOP w0.16: J1.14 49.58,57.27 87.51,57.27 J6.4 ; U17.70 v1(84.67,32.66)
  L3_MIX w0.16: J6.4 87.77,57.01 85.87,57.01 85.23,56.37 85.23,52.15 86.62,50.75 86.62,47.27 85.85,46.5 85.85,35.11 84.59,33.85 84.59,33.46 84.67,33.38 v1(84.67,32.66)
PTD4: length 77.5
  TOP w0.16: U17.69 84.82,32.16 85.13,32.46 85.13,32.69 85.82,33.38 85.82,37.38 v1(86.71,38.27)
  L3_MIX w0.16: v1(52.47,35.74) 52.47,30.37 53.75,29.09 53.75,23.34 52.25,21.84 52.25,19.74 52.82,19.16 52.82,17.56 52.57,17.3 52.57,6.92 J4.1
  BOTTOM w0.16: v1(52.47,35.74) 53.01,36.28 53.79,36.28 54.24,36.73 55.08,36.74 58.34,36.74 59.73,38.13 64.49,38.13 65.22,37.4 76.14,37.4 77.24,38.5 85.8,38.5 86.03,38.27 v1(86.71,38.27)
PTD5: length 52.4
  TOP w0.16: U17.33 v1(72.87,22.82)
  L3_MIX w0.16: v1(71.34,48.64) 71.34,44.95 72.24,44.05 72.24,23.46 v1(72.87,22.82)
  BOTTOM w0.16: v1(71.34,48.64) 56.35,48.64 52.05,52.93 52.05,54.63 J1.12
PTD6: length 42.6
  TOP w0.16: v1(69.87,9.32) 70.34,9.78 71.25,9.78 73.01,8.02 77.08,8.02 77.3,8.24 89.83,8.24 92.75,5.32 92.75,3.77 J5.18 ; R130.2 v1(69.87,17.39) 70.33,17.39 72.37,19.42 U17.32
  L3_MIX w0.16: v1(69.87,17.39) v1(69.87,9.32)
PTD7: length 43.2
  TOP w0.16: J5.16 90.15,3.83 90.15,6.28 88.99,7.44 78.23,7.44 77.56,6.78 76.41,6.78 76.4,6.78 70.72,6.78 68.65,8.85 v1(68.65,9.31) ; U17.31 71.87,19.93 70.5,18.56 69.38,18.56 v1(68.2,17.38) R131.2
  L3_MIX w0.16: v1(68.2,17.38) 68.2,9.77 v1(68.65,9.31)
PTD8: length 51.9
  TOP w0.16: v1(89.74,45.94) 83.78,51.9 J6.7 ; v1(76.1,24.5) 77.37,23.23 U17.42
  L3_MIX w0.16: v1(89.74,45.94) 91.19,44.49 91.19,35.78 90.96,35.54 90.96,28.37 90.6,28.02 v1(90.6,23.41)
  BOTTOM w0.16: v1(90.6,23.41) 77.2,23.41 v1(76.1,24.5)
PTD9: length 51.7
  TOP w0.16: v1(76.11,23.58) 76.87,22.82 U17.41
  L3_MIX w0.16: v1(89.68,20.62) 88.96,21.34 88.96,27.25 88.18,28.02 88.18,32.1 87.89,32.4 87.89,41.27 88.22,41.61 88.22,50.23 86.32,52.13 J6.5
  BOTTOM w0.16: v1(76.11,23.58) 77.38,22.31 87.99,22.31 v1(89.68,20.62)
PTD10: length 66.4
  TOP w0.16: U17.36 74.37,20.34 73.03,19 v1(73.03,17.42) 73.36,17.09 R166.1
  L3_MIX w0.16: v1(55.13,15.92) 55.13,20.31 58.13,23.31 58.13,43.49 57.11,44.51 57.11,54.65 J1.6
  BOTTOM w0.16: v1(55.13,15.92) 62.26,15.92 62.89,16.55 62.89,16.55 63.09,16.75 72.36,16.75 v1(73.03,17.42)
PTD11: length 67.1
  TOP w0.16: R168.1 v1(71.69,17.44) 71.69,18.14 73.87,20.32 U17.35
  L3_MIX w0.16: v1(53.96,15.91) 53.96,20.1 56.25,22.39 56.25,48.14 54.99,49.4 54.99,52.07 54.59,52.47 54.59,54.67 J1.8
  BOTTOM w0.16: v1(53.96,15.91) 54.51,16.45 61.95,16.45 62.65,17.15 65.57,17.15 66.71,18.29 70.84,18.29 v1(71.69,17.44)
PTD12: length 52.9
  TOP w0.16: U17.34 v1(73.37,24.01)
  L3_MIX w0.16: v1(73.9,49.71) 73.9,44.87 73.37,44.34 73.37,38.83 73.07,38.53 73.07,37.87 73.37,37.57 v1(73.37,24.01)
  BOTTOM w0.16: J1.10 54.55,54.67 54.55,52.97 57.82,49.71 v1(73.9,49.71)
PTD13: length 59.2
  TOP w0.16: v1(58.7,18.49) 59.76,18.49 60.94,19.67 65.01,19.67 67.62,22.28 U17.25
  L3_MIX w0.16: J2.1 41.62,52.29 46.06,47.85 46.06,36.93 47.06,35.93 47.06,35.58 47.06,35.3 47.06,35.3 47.06,34.52 47.06,33.96 47.06,33.96 47.06,33.88 45.49,32.31 45.49,29.16 45.49,28.88 45.61,28.75 45.61,28.32 v1(44.31,27.02)
  BOTTOM w0.16: v1(58.7,18.49) 50.75,26.44 44.88,26.44 v1(44.31,27.02)
PTD14: length 58.7
  TOP w0.16: v1(59.64,19.23) 60.64,20.23 64.16,20.23 65.42,21.48 65.42,22.48 66.59,23.66 U17.24
  L3_MIX w0.16: J2.3 39.08,52.26 45.38,45.95 45.38,36.58 46.38,35.58 46.38,34.52 46.38,34.24 44.41,32.26 v1(44.41,29.38)
  BOTTOM w0.16: v1(59.64,19.23) 56.97,21.9 55.96,21.9 51.08,26.78 45.29,26.78 44.41,27.65 v1(44.41,29.38)
PTD15: length 59.9
  TOP w0.16: R154.1 63.57,21.08 63.57,21.07 v1(64.03,21.07) 64.03,22.03 66.65,24.66 U17.22
  L3_MIX w0.16: v1(45.37,27.35) 45.95,27.93 45.95,28.89 45.83,29.02 45.83,29.02 45.83,29.3 45.83,29.3 45.83,32.17 47.4,33.74 47.4,33.83 47.4,33.83 47.4,34.08 47.4,34.38 47.4,34.56 47.4,35.16 47.4,35.16 47.4,35.72 47.4,36.07 47.2,36.27 46.4,37.07 46.4,48.4 43.61,51.2 43.61,53.93 J2.2
  BOTTOM w0.16: v1(64.03,21.07) 63,21.07 61.88,22.2 59.94,22.2 59.42,22.73 55.61,22.73 51.22,27.11 46.06,27.11 45.83,27.35 v1(45.37,27.35)
PTD16: length 58.2
  TOP w0.16: U17.21 66.41,25.16 v1(63.98,22.73) R155.1
  L3_MIX w0.16: v1(45.15,28.56) 45.15,28.74 45.15,28.74 45.15,29.3 45.15,29.3 45.15,32.52 46.72,34.1 46.72,34.52 46.72,35.44 46.72,35.72 45.72,36.72 45.72,47.16 40.26,52.62 40.26,54.73 J2.4
  BOTTOM w0.16: v1(63.98,22.73) 63.34,23.37 55.5,23.37 51.41,27.47 46.25,27.47 v1(45.15,28.56)
PTD17: length 37
  TOP w0.16: U17.20 v1(76.1,25.66)
  L3_MIX w0.16: v1(76.1,25.66) 76.1,32.65 77.1,33.64 77.1,39.49 76.44,40.15 76.44,44.99 76.16,45.27 J6.13
PTE0: length 73.9
  TOP w0.16: v1(72.73,39.41) 72.73,38.9 72.37,38.54 U17.94
  L3_MIX w0.16: v1(44.67,35.73) 44.28,35.73 44.03,35.48 43.56,35.48 42,33.91 42,33.68 38.42,30.1 38.42,29.14 32.6,23.32 32.6,21.88 32.94,21.54 32.94,11.93 32.73,11.72 32.73,9.94 32.47,9.69 32.47,9.44 31.73,8.7 31.73,3.83 J3.6
  BOTTOM w0.16: v1(72.73,39.41) 64.47,39.41 63.73,40.14 62.56,40.14 61.52,41.19 61.15,41.19 61.02,41.32 60.64,41.32 60.37,41.05 60.37,40.57 56.88,37.08 54.94,37.08 54.94,37.08 54.1,37.07 53.65,36.61 45.55,36.61 v1(44.67,35.73)
PTE1: length 62.5
  TOP w0.16: U17.93 v1(72.87,34.96)
  L3_MIX w0.16: v1(97.47,32.8) 96.74,32.07 96.74,13.92 93.83,11.02 93.83,9.2 90.13,5.5 90.13,3.85 J5.14
  BOTTOM w0.16: v1(97.47,32.8) 96.71,33.57 93.31,33.57 91.99,34.89 90.05,34.89 89.81,34.64 85.6,34.64 84.61,33.64 81.66,33.64 81.59,33.72 81.14,33.72 80.43,34.43 80.07,34.43 79.84,34.19 73.64,34.19 v1(72.87,34.96)
PTE2: length 49.1
  TOP w0.16: U17.85 76.87,38.37 77.44,38.94 77.44,40.15 77.76,40.47 v1(77.77,40.47)
  L3_MIX w0.16: v1(77.77,40.47) 77.77,33.46 76.68,32.37 76.68,31.59 76.49,31.39 76.49,31.01 76.68,30.82 76.68,14.05 76.4,13.77 v1(76.4,8.82)
  BOTTOM w0.16: J4.13 66,6.36 67.44,7.8 70.14,7.8 70.24,7.71 75.28,7.71 v1(76.4,8.82)
PTE3: length 55.9
  TOP w0.16: v1(65.42,26.05) 66.03,26.66 U17.18
  L3_MIX w0.16: v1(65.42,26.05) 66.38,27.01 66.38,31.15 65.87,31.66 65.87,32.98 66.89,33.99 66.89,41.61 66.89,41.61 66.89,43.42 66.58,43.74 v1(66.58,53.54)
  BOTTOM w0.16: v1(66.58,53.54) 65.42,54.7 65.42,56.37 64.33,57.46 46.02,57.46 45.68,57.12 J1.16
PTE4: length 31.1
  TOP w0.16: U17.9 65.94,31.16 65.34,31.76 65.34,34.71 v1(64.11,35.94) 63.65,35.94 63.64,35.94 R137.2
  L3_MIX w0.16: v1(64.11,35.94) 64.78,36.61 64.78,45.34 65.24,45.8 65.24,54.16 67,55.92 J6.20
PTE5: length 34.2
  TOP w0.16: U17.8 66.27,31.66 65.68,32.25 65.68,35.99 v1(64.05,37.62) R136.2
  L3_MIX w0.16: v1(64.05,37.62) 64.44,38.01 64.44,45.48 64.72,45.75 64.72,54.11 67.62,57.01 69.99,57.01 J6.18
PTE6: length 55.8
  TOP w0.16: U17.84 77.37,38.23 77.77,38.63 77.77,39.82 78.52,40.57 v1(81.1,40.57)
  L3_MIX w0.16: v1(81.1,40.57) 81.1,33.6 81.2,33.7 81.59,33.7 81.86,33.43 81.86,33.04 81.84,33.03 81.84,33.01 81.57,32.74 81.19,32.74 81.1,32.83 81.1,31.97 81.75,31.32 81.75,30.94 81.65,30.83 81.65,13.57 82.32,12.9 v1(82.32,8.82)
  BOTTOM w0.16: J4.15 70.23,6.8 75.88,6.8 76.88,7.8 79.02,7.8 79.45,8.23 81.72,8.23 v1(82.32,8.82)
PTE7: length 80.4
  TOP w0.16: v1(76.95,46.99) 75.37,48.57 72.52,48.57 71.9,49.19 40.24,49.19 39.38,50.04 34,50.04 33.61,50.44 33.14,50.9 32.86,50.9 32.54,50.9 32.54,50.9 31.6,50.9 31.59,50.9 29.85,50.9 27.58,53.16 27.58,54.71 J2.14 ; U17.59 v1(78.38,27.16)
  L3_MIX w0.16: v1(76.95,46.99) 78.28,45.66 78.28,28.02 78.38,27.92 v1(78.38,27.16)
PTE8: length 73.5
  TOP w0.16: v1(60,51.44) 40.85,51.44 40.22,52.07 36.3,52.07 35.24,53.13 35.24,54.68 J2.8 ; R135.2 62.16,16.48 v1(62.16,17.5) 64.58,17.5 68.49,21.41 U17.26
  L3_MIX w0.16: v1(60,51.44) 60,40.75 61.52,39.23 61.52,18.13 v1(62.16,17.5)
PTE9: length 46.6
  TOP w0.16: U17.23 68.69,24.16 68.85,24 68.85,22.52 65.11,18.79 v1(63.94,18.79) R529.2
  BOTTOM w0.16: v1(63.94,18.79) 61.33,18.79 60,17.47 54.08,17.47 53.09,16.47 53.09,16.09 51.7,14.7 51.27,14.7 45.57,9 40.18,9 36.81,5.63 36.81,3.86 J3.8
PTE10: length 41.8
  TOP w0.16: U17.6 v1(66.34,32.66) ; R567.2 93.33,40.67 v1(93.32,40.66) R543.1
  L3_MIX w0.16: v1(93.69,30.77) 93.84,30.93 93.84,31.87 93.74,31.97 93.74,37 93.79,37.05 93.79,40.2 93.76,40.22 v1(93.32,40.66)
  BOTTOM w0.16: v1(66.34,32.66) 67.2,31.79 75.4,31.79 76.54,30.64 88.61,30.64 88.75,30.79 91.09,30.79 91.23,30.65 91.59,30.65 91.71,30.77 v1(93.69,30.77)
PTE11: length 32.6
  TOP w0.16: R568.2 88.82,39.59 R544.1 v1(88.69,40.59) ; U17.5 v1(68.92,33.16)
  L3_MIX w0.16: v1(88.69,40.59) 88.69,36.74 88.61,36.66 88.61,36 88.68,35.93 v1(88.68,32.73)
  BOTTOM w0.16: v1(68.92,33.16) 69.78,32.3 75.4,32.3 76.03,31.67 86.62,31.67 86.82,31.47 87.42,31.47 v1(88.68,32.73)
PTE12: length 44.5
  TOP w0.16: U17.19 66.55,26.16 v1(63.96,23.57) ; J6.15 72.41,54.59 v1(66.33,54.59)
  L3_MIX w0.16: v1(63.96,23.57) 63.96,32.03 65.75,33.82 65.75,54.01 v1(66.33,54.59)
PTE13: length 42.5
  TOP w0.16: R532.2 v1(78.83,13.85) ; U17.7 v1(77.43,32.16)
  L3_MIX w0.16: J5.8 80.04,3.78 80.04,5.66 78.83,6.87 v1(78.83,13.85) 79.33,14.35 79.33,19.35 77.84,20.84 77.84,27.64 77.43,28.04 v1(77.43,32.16)
PTE14: length 34.9
  TOP w0.16: U17.17 v1(77.27,27.16)
  L3_MIX w0.16: v1(77.27,27.16) 77.27,18.27 77.56,17.98 77.56,17.73 77.65,17.65 77.65,17.26 77.56,17.18 77.56,3.72 J5.6
PTE15: length 40.9
  TOP w0.16: U17.2 72.52,34.66 72.68,34.5 73.06,34.5 73.21,34.66 v1(73.97,34.66)
  L3_MIX w0.16: v1(73.97,34.66) 73.71,34.4 73.71,24.49 73.83,24.37 73.83,19.87 72.57,18.6 72.57,14.93 72.32,14.67 72.32,8.33 74.89,5.75 74.89,3.85 J5.4
PTE16: length 37.7
  TOP w0.16: v1(71.7,35.16) 71.24,35.16 U17.1
  L3_MIX w0.16: v1(71.7,35.16) 71.7,20.9 72.22,20.38 72.22,15.06 71.98,14.82 71.98,6.62 72.29,6.3 72.29,3.91 J5.2
PWR_LED: length 1.8
  TOP w0.254: D3.A R56.1
RGB_BLUE: length 89.4
  TOP w0.16: R95.2 105.9,7.48 104.07,9.31 v1(97.49,9.31) ; R156.2 v1(60.4,39.29)
  L3_MIX w0.16: v1(97.49,9.31) 97.49,32.12 97.93,32.56 97.93,33 97.49,33.44 97.49,39.02 v1(95.67,40.85)
  BOTTOM w0.16: v1(60.4,39.29) 62.62,39.29 63.42,38.49 68.34,38.49 69.1,37.74 75.93,37.74 77.14,38.94 85.56,38.94 86.46,39.84 94.67,39.84 v1(95.67,40.85)
RGB_GREEN: length 70.3
  TOP w0.16: R155.2 v1(60.33,22.73) ; R96.2 106.73,5.7 103.62,8.81 96.9,8.81 96.49,9.23 v1(96.49,9.99)
  BOTTOM w0.16: v1(60.33,22.73) 62.15,22.73 62.85,22.03 64.38,22.03 67.84,25.49 72.71,25.49 76.78,21.43 82.36,21.43 85.79,17.99 94.65,17.99 96.9,15.75 96.9,11.02 96.49,10.61 v1(96.49,9.99)
RGB_RED: length 69.7
  TOP w0.16: R154.2 v1(60.36,21.08) ; R97.2 107.4,3.93 102.99,8.34 96.29,8.34 95.86,8.76 v1(95.86,9.23)
  BOTTOM w0.16: v1(60.36,21.08) 60.82,20.61 64.22,20.61 64.81,21.21 64.81,21.39 67.21,23.79 72.68,23.79 76.01,20.45 82.4,20.45 85.49,17.36 93.56,17.36 96.23,14.68 96.23,13.52 95.86,13.14 v1(95.86,9.23)
RST_TGTMCU_B: length 170
  TOP w0.16: J104.3 8.92,48.99 10.85,48.99 R5.2 ; J104.3 6.77,47.82 5.84,48.75 5.84,49.84 5.09,50.59 R4.2 4.52,51.58 4.02,52.08 D1.C ; J104.3 U1.7 ; U17.97 70.87,38.58 68.63,40.82 68.63,44.05 68.47,44.21 v1(68.47,44.67) ; v1(47.79,4.82) 46.81,3.85 34.25,3.85 J3.5 31.71,3.85 26.38,3.85 24.18,6.05 13.12,6.05 11.69,7.48 v1(11.69,12.76) ; R563.2 v1(47.79,21.08)
  L3_MIX w0.16: v1(47.79,4.82) 48.17,5.2 48.17,10.41 47.08,11.5 47.08,17.35 47.32,17.59 47.32,20.62 v1(47.79,21.08) 47.79,22.6 47.19,23.19 47.19,24.64 49.52,26.96 50.06,26.96 51.15,28.05 51.15,36.33 50.05,37.43 50.05,43.89 50.54,44.37 J14.10
  BOTTOM w0.16: v1(68.47,44.67) 68.01,44.67 67.85,44.84 56.21,44.84 55.8,45.25 52.77,45.25 J14.10 ; v1(11.69,12.76) 10.56,12.76 8.79,14.53 8.79,24.05 6.68,26.17 6.68,46.76 J104.3
SBC_CAN_RX: length 29.4
  TOP w0.16: v1(60.31,35.76) 60.49,35.94 R137.1 ; U30.6 v1(42.69,25.09)
  L3_MIX w0.16: v1(42.69,25.09) 42.69,25.8 42.85,25.95 42.85,26.84 42.48,27.21 42.48,28.1 43.19,28.81 43.19,32.72 44.03,33.57 44.03,34.07 44.88,34.92 45.26,34.92 v1(45.59,35.25)
  BOTTOM w0.16: v1(60.31,35.76) 59.43,35.76 59.26,35.59 59.06,35.39 55.64,35.39 55.51,35.26 55.51,35.26 55.44,35.19 55.24,34.99 55.09,34.84 53.79,34.84 51.56,34.84 50.84,34.13 46.71,34.13 v1(45.59,35.25)
SBC_CAN_RX_LS: length 27.8
  TOP w0.16: TP20.1 v1(41.29,18.74) ; U19.7 v1(20.89,18.74) ; U30.3 v1(41.76,23)
  L3_MIX w0.16: v1(41.29,18.74) 41.29,22.04 41.76,22.51 v1(41.76,23)
  BOTTOM w0.16: v1(20.89,18.74) v1(41.29,18.74)
SBC_CAN_TX: length 32
  TOP w0.16: U30.7 41.76,25.66 41.87,25.77 42.68,25.77 42.77,25.68 v1(43.23,25.68) ; R136.1 v1(60.44,37.62)
  L3_MIX w0.16: v1(43.23,25.68) 43.23,26.93 42.81,27.35 42.81,27.96 43.08,28.23 43.52,28.67 43.52,32.58 44.4,33.45 44.4,33.52 v1(44.72,33.85) ; v1(60.39,34.74) 60.87,35.21 60.87,37.19 v1(60.44,37.62)
  BOTTOM w0.16: v1(44.72,33.85) 45.12,33.45 51.12,33.45 51.77,34.1 55.31,34.1 55.79,34.59 55.92,34.71 57.7,34.71 57.87,34.54 58.05,34.71 59.34,34.71 59.37,34.74 v1(60.39,34.74)
SBC_CAN_TX_LS: length 31.3
  TOP w0.16: TP21.1 v1(41.33,16.74) ; v1(21.48,15.71) 20.95,16.24 U19.2 ; U30.2 v1(40.83,23.79)
  L3_MIX w0.16: v1(41.33,16.74) 40.82,17.24 40.82,22.19 41.15,22.52 41.15,23.46 v1(40.83,23.79)
  BOTTOM w0.16: v1(41.33,16.74) 39.85,16.74 38.82,15.71 v1(21.48,15.71)
SBC_CS: length 53.1
  TOP w0.16: v1(52.19,19.12) 51.73,19.12 51.09,19.77 51.09,19.95 50.61,20.43 U31.4 ; R129.1 90.18,30.25 v1(90.49,29.94)
  L3_MIX w0.16: v1(53.28,27.28) 53.28,23.35 51.91,21.98 51.91,19.4 v1(52.19,19.12)
  BOTTOM w0.16: v1(53.28,27.28) 53.28,26.68 54.97,24.99 57.35,24.99 59.95,27.59 64.69,27.59 64.86,27.41 71.96,27.41 73.37,28.82 89.37,28.82 v1(90.49,29.94)
SBC_CS_LS: length 37
  TOP w0.16: v1(39.8,15.75) TP33.1 41.5,15.72 41.71,15.51 43.76,15.51 43.9,15.38 44.28,15.38 44.41,15.51 45.27,15.51 45.98,16.22 46.19,16.22 48.43,18.45 48.43,19.83 49.03,20.43 U31.3 ; U19.20 16.58,15.28 v1(16.78,15.09)
  BOTTOM w0.16: v1(39.8,15.75) 39.25,15.2 22.61,15.2 22.5,15.09 v1(16.78,15.09)
SBC_LIMP: length 33.7
  TOP w0.16: R532.1 v1(78.83,17.48) ; v1(53.6,13.59) 53,13.59 51,15.59 51,16.92 50.61,17.32 U33.4
  BOTTOM w0.16: v1(78.83,17.48) 78.33,17.97 76.64,17.97 75.09,16.41 63.23,16.41 62.4,15.58 56.78,15.58 54.8,13.59 v1(53.6,13.59)
SBC_LIMP_LS: length 42.2
  TOP w0.16: R536.2 36.3,21.37 36.34,21.34 36.36,21.34 v1(36.99,20.71) ; U19.11 v1(16.58,20.82) ; R566.1 47.71,16.04 v1(47.64,16.12) 47.31,15.79 47.31,15.53 47.04,15.26 47.04,14.93 TP502.1
  BOTTOM w0.16: v1(47.64,16.12) 47.06,15.54 46.33,15.54 45.32,16.55 42.13,16.55 41.97,16.71 41.97,19.89 41.55,20.31 38.65,20.31 38.38,20.04 37.96,20.04 37.91,20.09 37.61,20.09 v1(36.99,20.71) 36.6,21.1 35.72,21.1 35.32,20.69 35.04,20.69 33.11,20.69 32.92,20.89 32.92,20.89 32.47,21.34 31.83,21.34 31.83,21.33 31.64,21.33 31.35,21.04 30.31,21.04 30.02,21.34 20.93,21.34 20.42,20.82 19,20.82 18.64,21.19 16.95,21.19 v1(16.58,20.82)
SBC_MISO: length 57
  TOP w0.16: v1(90.5,33.03) 89.92,33.6 R125.2 ; v1(54.2,21.59) 53.46,21.59 52.09,22.96 51.88,22.96 51.2,23.65 U29.4
  L3_MIX w0.16: v1(53.4,20.05) 54.7,21.34 54.7,29.36 v1(55.79,30.45)
  BOTTOM w0.16: v1(54.2,21.59) 54.2,20.84 v1(53.4,20.05) ; v1(90.5,33.03) 89.03,33.03 88.88,33.19 88.49,33.19 88.1,32.8 85.85,32.8 85.24,32.19 80.17,32.19 79.32,33.04 70.68,33.04 69.11,34.62 66.67,34.62 63.79,31.73 58.38,31.73 57.1,30.45 v1(55.79,30.45)
SBC_MISO_LS: length 32
  TOP w0.16: U19.9 v1(20.87,19.74) ; v1(39.91,19.74) TP23.1 42.79,19.74 44.92,21.87 48.27,21.87 48.96,22.56 48.96,23.32 49.29,23.65 U29.3
  BOTTOM w0.16: v1(39.91,19.74) 38.56,19.74 38.52,19.7 37.82,19.7 37.78,19.74 22.8,19.74 22.8,19.74 22.34,19.74 22.34,19.74 v1(20.87,19.74)
SBC_MOSI: length 70.3
  TOP w0.16: R126.2 v1(90.45,31.93) ; U26.6 v1(39.12,25.07)
  L3_MIX w0.16: v1(90.72,37.34) 90.72,36.69 90.85,36.56 90.85,35.92 90.03,35.1 90.03,32.35 v1(90.45,31.93) ; v1(43.48,34.27) 43.22,34 43.09,34 42.67,33.59 42.67,29.31 40.11,26.75 40.11,25.93 40.24,25.81 40.24,25.42 39.97,25.15 39.93,25.15 39.85,25.07 v1(39.12,25.07)
  BOTTOM w0.16: v1(90.72,37.34) 90.39,37.66 88.3,37.66 87.08,36.44 85.74,36.44 84.82,37.37 83.4,37.37 82.76,36.72 64.45,36.72 64.44,36.74 59.46,36.74 58.78,36.06 55.36,36.06 55.35,36.05 54.52,36.05 53.65,35.18 49.37,35.18 48.84,35.71 45.3,35.71 44.86,35.26 44.47,35.26 44.21,35.53 43.61,35.53 43.16,35.08 43.16,34.6 v1(43.48,34.27)
SBC_MOSI_LS: length 28
  TOP w0.16: v1(21.53,16.54) 21.32,16.74 U19.3 ; U26.3 v1(38.19,22.98) ; v1(38.19,17.75) 38.65,17.75 38.65,17.76 TP25.1
  L3_MIX w0.16: v1(38.19,17.75) 38.19,19.82 38.63,20.26 38.63,21.68 38.19,22.12 v1(38.19,22.98)
  BOTTOM w0.16: v1(38.19,17.75) 37.62,17.18 22.18,17.18 v1(21.53,16.54)
SBC_RST: length 41.7
  TOP w0.16: TP24.1 v1(17.51,14.01) ; R565.1 45.95,16.89 45.47,16.41 45.46,16.41 v1(45.13,16.09) ; U19.8 v1(21.4,19.24)
  BOTTOM w0.16: v1(21.4,19.24) 20.28,19.24 19.42,18.38 19.42,17.46 18.71,16.75 17.79,16.75 16.32,15.28 16.32,14.74 17.05,14.01 v1(17.51,14.01) 22.03,14.01 22.88,14.86 43.9,14.86 v1(45.13,16.09)
SBC_SCK: length 62.4
  TOP w0.16: U26.7 38.19,25.63 38.32,25.77 39.16,25.77 39.32,25.62 v1(39.78,25.62) ; R124.2 v1(89.41,36.33)
  L3_MIX w0.16: v1(43.82,35.02) 43.58,35.02 42.34,33.77 42.34,29.45 39.78,26.89 v1(39.78,25.62)
  BOTTOM w0.16: v1(89.41,36.33) 87.44,36.33 87.22,36.11 85.74,36.11 85.47,35.83 80.26,35.83 80.08,36.01 70.94,36.01 70.1,35.18 69.5,35.18 69.39,35.29 64.83,35.29 64.23,34.68 61.1,34.68 60.58,35.2 59.35,35.2 59.2,35.05 55.78,35.05 55.65,34.92 55.65,34.92 55.17,34.44 51.63,34.44 50.98,33.79 46.05,33.79 44.91,34.93 43.92,34.93 v1(43.82,35.02)
SBC_SCK_LS: length 29.7
  TOP w0.16: U26.2 v1(37.26,23.77) ; v1(38.17,20.55) 41.72,20.55 TP27.1 ; U19.10 v1(19.88,21.31)
  L3_MIX w0.16: v1(38.17,20.55) 38.17,21.66 37.7,22.13 37.7,23.32 v1(37.26,23.77)
  BOTTOM w0.16: v1(19.88,21.31) 20.79,22.21 30.15,22.21 30.42,22.48 31.08,22.48 31.25,22.31 32.31,22.31 32.58,22.04 32.58,21.83 33.39,21.03 35.18,21.03 35.58,21.44 37.13,21.44 37.69,20.88 37.84,20.88 v1(38.17,20.55)
SDA_EXTAL: length 5.4
  TOP w0.16: Y1.3 21.74,33.58 21.3,33.58 C23.1 20.55,34.32 20.55,36.2 U8.17
SDA_JTAG_TCLK: length 11.7
  TOP w0.16: J12.4 15.44,29.36 14.29,30.51 14.27,30.51 14,30.78 14,30.8 13.83,30.97 13.83,34.37 U8.12
SDA_JTAG_TDI: length 8.3
  TOP w0.16: U8.13 v1(17.23,37.07)
  BOTTOM w0.16: J12.8 15.44,31.9 14.91,32.43 14.89,32.43 14.64,32.68 14.64,33.69 17.23,36.28 v1(17.23,37.07)
SDA_JTAG_TDO: length 9.4
  TOP w0.16: U8.14 14.57,33.69 14.57,31.5 14.63,31.44 14.66,31.44 14.93,31.17 14.93,31.14 15.44,30.63 J12.6
SDA_JTAG_TMS: length 17.6
  TOP w0.16: R77.2 14.68,28.08 14.69,28.09 J12.2 17.33,26.81 19.45,26.81 20.03,27.39 20.03,32.88 18.31,34.6 18.31,36.73 U8.15
SDA_LED: length 2.7
  TOP w0.16: D2.C 22.74,42.45 21.91,42.45 U8.29
SDA_LED_R: length 1.3
  TOP w0.16: R12.2 24.28,43.99 D2.A
SDA_RST: length 18.4
  TOP w0.16: v1(26.69,34.76) 26.69,34.76 R62.1 25.69,35.76 25.69,35.76 R57.2 24.86,36.59 24.86,36.59 TP12.1 21.16,37.01 U8.19
  BOTTOM w0.16: v1(26.69,34.76) 17.63,34.76 J12.10
SDA_RST_LED: length 1.4
  TOP w0.16: D1.A R2.1
SDA_RST_TGTMCU_B: length 15.5
  TOP w0.16: U8.21 21.83,37.76 23.62,37.76 v1(24.18,38.33)
  BOTTOM w0.16: J105.2 20.63,46.19 20.63,44.7 21.73,43.6 21.73,39.66 23.06,38.33 v1(24.18,38.33)
SDA_RST_TGTMCU_J_B: length 11.6
  TOP w0.16: U1.2 R3.2 10.18,51.43 11.9,51.43 12.82,50.52 R5.1 J104.1 J105.1
SDA_RX_EN: length 3.7
  TOP w0.16: U4.5 R15.2 32.02,44.44 R16.1 32.8,44.43 v1(32.96,44.59)
SDA_SPI0_CS: length 9.7
  TOP w0.16: U8.23 22.5,38.5 22.69,38.5 23.98,39.79 25.42,39.79 25.78,40.15 TP7.1 R38.2
SDA_SPI0_RST_B: length 10.1
  TOP w0.16: U8.22 22.17,38.13 23.17,38.13 24.2,39.15 TP8.1 25.93,39.15 26.18,39.4 30.23,39.4 30.48,39.15 R41.2
SDA_SPI0_SCK: length 9.4
  TOP w0.16: 22.1,40.52 22.63,41.05 v1(25.08,41.05) ; U10.3 28.48,37.62 28.04,37.19 v1(27.39,37.19)
  BOTTOM w0.16: v1(27.39,37.19) 27.16,37.41 27.16,37.96 25.08,40.04 v1(25.08,41.05)
SDA_SPI0_SIN: length 11
  TOP w0.16: U2.5 v1(27.52,47.85) 27.19,47.52 27.19,45.54 23.59,41.95 22.12,41.95 U8.28
SDA_SPI0_SOUT: length 7.5
  TOP w0.16: U8.27 22.44,41.56 v1(23.99,41.56) 26.4,41.56 27.3,40.66 U7.3
SDA_SWD_EN: length 2.5
  TOP w0.16: U9.6 34.03,39.3 33.88,39.15 R47.1 R41.1
SDA_SWD_EN_B: length 18.4
  TOP w0.16: v1(35.58,37.16) R49.2 ; U8.16 v1(19.63,36.21)
  BOTTOM w0.16: v1(35.58,37.16) 34.63,37.16 33.09,35.62 26.2,35.62 25.61,36.21 v1(19.63,36.21)
SDA_SWD_EN_B_R: length 3.1
  TOP w0.16: U9.1 35.58,39.3 35.73,39.15 R42.2 36.6,39.12 v1(36.03,38.55) 36.02,38.55 36.02,38.53 R49.1
SDA_SWD_EN_R: length 3.7
  TOP w0.16: U10.5 R52.2 31.03,38.13 R51.1 32.03,38.13 R47.2
SDA_SWD_OE: length 2.5
  TOP w0.16: R38.1 32.02,40.15 33.03,40.15 R35.1 33.9,40.15 34.05,40 U9.4
